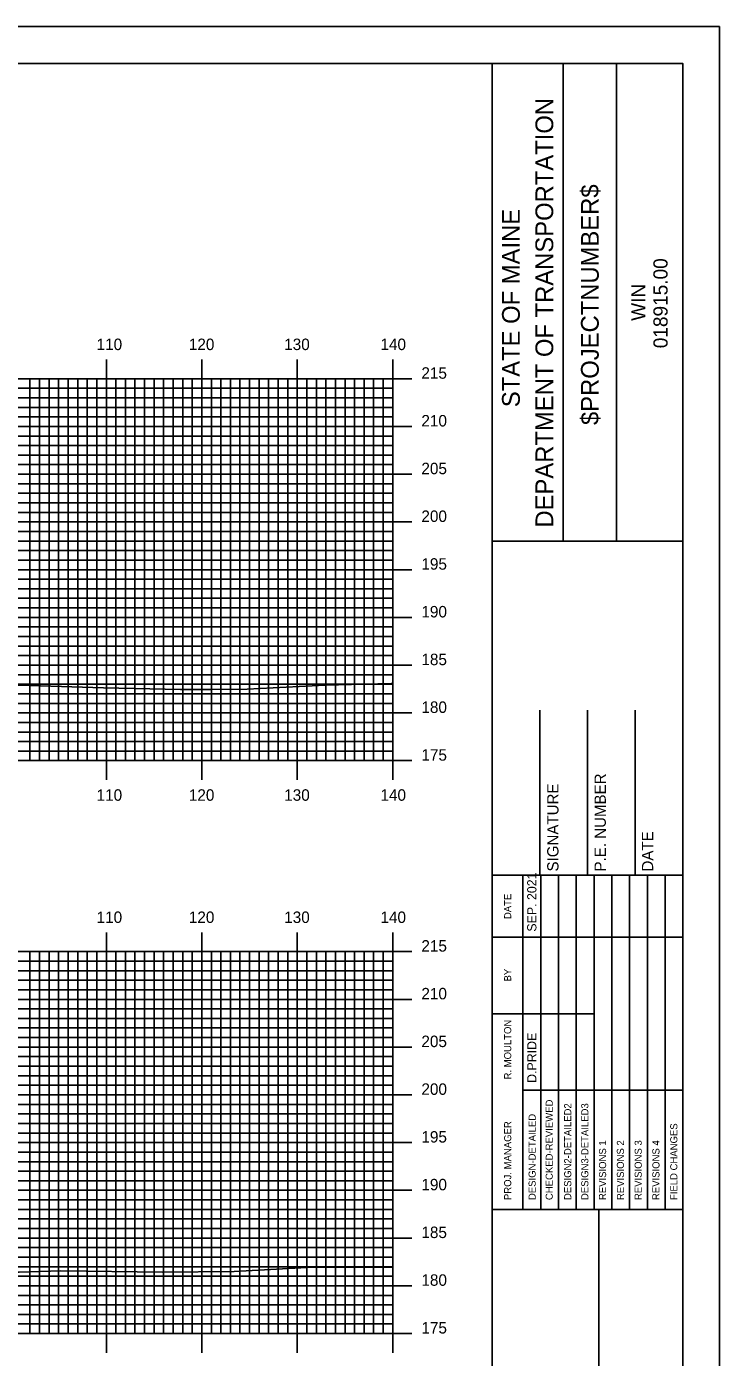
# Model space of a CAD drawing. Extents: x 1809800 to 1810143, y 442591 to 442811.
# Drawn here: x 1810067 to 1810139.6, y 442671.2 to 442810.5 of the extents above; entities that cross this region are included whole.
import ezdxf

# ---------------------------------------------------------------- set-up
doc = ezdxf.new("R2010")
doc.units = 0
for name, color, linetype in [('BORDER', 7, 'Continuous'), ('H_V ANNOTATION', 7, 'Continuous'), ('MAJOR', 7, 'Continuous'), ('MINOR', 7, 'Continuous'), ('PLOT BOUNDARY', 7, 'Continuous'), ('S_Roadway_Centerline', 7, 'Continuous')]:
    doc.layers.add(name, color=color, linetype=linetype)

msp = doc.modelspace()

# ---------------------------------------------------------------- linework, layer by layer
at = {"layer": 'BORDER'}
for p, q in [((1810115.75, 442596.67), (1810115.75, 442806.67)), ((1810123.21, 442756.66), (1810123.21, 442806.66)), ((1810128.8, 442756.66), (1810128.8, 442806.66)), ((1810115.75, 442756.65), (1810135.75, 442756.65)), ((1810120.75, 442721.67), (1810120.75, 442738.97)), ((1810125.75, 442721.67), (1810125.75, 442738.97)), ((1810130.75, 442721.67), (1810130.75, 442738.97)), ((1810115.75, 442721.67), (1810135.75, 442721.67)), ((1810115.75, 442686.67), (1810135.75, 442686.67)), ((1810126.93, 442616.67), (1810126.93, 442686.67))]:
    msp.add_line(p, q, dxfattribs=at)
msp.add_lwpolyline([(1809815.75, 442596.67), (1810135.75, 442596.67), (1810135.75, 442806.67), (1809815.75, 442806.67)], close=True, dxfattribs=at)
for points in [[(1810118.98, 442715.17), (1810118.98, 442721.67)], [(1810120.85, 442686.68), (1810120.85, 442721.67)], [(1810122.71, 442721.67), (1810122.71, 442686.68)], [(1810124.57, 442686.68), (1810124.57, 442721.67)], [(1810126.44, 442686.68), (1810126.44, 442721.67)], [(1810128.3, 442686.68), (1810128.3, 442721.67)], [(1810130.16, 442686.68), (1810130.16, 442721.67)], [(1810132.03, 442686.68), (1810132.03, 442721.67)], [(1810133.89, 442686.68), (1810133.89, 442721.67)], [(1810118.98, 442686.68), (1810118.98, 442720.26)], [(1810115.75, 442715.17), (1810135.75, 442715.17)], [(1810115.75, 442707.17), (1810118.98, 442707.17)], [(1810118.98, 442707.17), (1810126.43, 442707.17)], [(1810118.98, 442699.17), (1810135.75, 442699.17)]]:
    msp.add_lwpolyline(points, dxfattribs=at)
at = {"layer": 'MAJOR'}
for p, q in [((1810075.35, 442775.67), (1810075.35, 442773.67)), ((1810085.35, 442775.67), (1810085.35, 442773.67)), ((1810095.35, 442775.67), (1810095.35, 442773.67)), ((1810105.35, 442775.67), (1810105.35, 442773.67)), ((1809825.35, 442773.67), (1810105.35, 442773.67)), ((1809825.35, 442773.67), (1810105.35, 442773.67)), ((1810075.35, 442733.67), (1810075.35, 442773.67)), ((1810085.35, 442733.67), (1810085.35, 442773.67)), ((1810095.35, 442733.67), (1810095.35, 442773.67)), ((1810107.35, 442773.67), (1810103.35, 442773.67)), ((1810105.35, 442733.67), (1810105.35, 442773.67)), ((1810105.35, 442733.67), (1810105.35, 442773.67)), ((1809825.35, 442768.67), (1810105.35, 442768.67)), ((1810107.35, 442768.67), (1810103.35, 442768.67)), ((1809825.35, 442763.67), (1810105.35, 442763.67)), ((1810107.35, 442763.67), (1810103.35, 442763.67)), ((1809825.35, 442758.67), (1810105.35, 442758.67)), ((1810107.35, 442758.67), (1810103.35, 442758.67)), ((1809825.35, 442753.67), (1810105.35, 442753.67)), ((1810107.35, 442753.67), (1810103.35, 442753.67)), ((1809825.35, 442748.67), (1810105.35, 442748.67)), ((1810107.35, 442748.67), (1810103.35, 442748.67)), ((1809825.35, 442743.67), (1810105.35, 442743.67)), ((1810107.35, 442743.67), (1810103.35, 442743.67)), ((1809825.35, 442738.67), (1810105.35, 442738.67)), ((1810107.35, 442738.67), (1810103.35, 442738.67)), ((1809825.35, 442733.67), (1810105.35, 442733.67)), ((1809825.35, 442733.67), (1810105.35, 442733.67)), ((1810075.35, 442731.66), (1810075.35, 442733.67)), ((1810085.35, 442731.66), (1810085.35, 442733.67)), ((1810095.35, 442731.66), (1810095.35, 442733.67)), ((1810107.35, 442733.67), (1810103.35, 442733.67)), ((1810105.35, 442731.66), (1810105.35, 442733.67)), ((1810075.35, 442715.67), (1810075.35, 442713.67)), ((1810085.35, 442715.67), (1810085.35, 442713.67)), ((1810095.35, 442715.67), (1810095.35, 442713.67)), ((1810105.35, 442715.67), (1810105.35, 442713.67)), ((1809825.35, 442713.67), (1810105.35, 442713.67)), ((1809825.35, 442713.67), (1810105.35, 442713.67)), ((1810075.35, 442673.67), (1810075.35, 442713.67)), ((1810085.35, 442673.67), (1810085.35, 442713.67)), ((1810095.35, 442673.67), (1810095.35, 442713.67)), ((1810107.35, 442713.67), (1810103.35, 442713.67)), ((1810105.35, 442673.67), (1810105.35, 442713.67)), ((1810105.35, 442673.67), (1810105.35, 442713.67)), ((1809825.35, 442708.67), (1810105.35, 442708.67)), ((1810107.35, 442708.67), (1810103.35, 442708.67)), ((1809825.35, 442703.67), (1810105.35, 442703.67)), ((1810107.35, 442703.67), (1810103.35, 442703.67)), ((1809825.35, 442698.67), (1810105.35, 442698.67)), ((1810107.35, 442698.67), (1810103.35, 442698.67)), ((1809825.35, 442693.67), (1810105.35, 442693.67)), ((1810107.35, 442693.67), (1810103.35, 442693.67)), ((1809825.35, 442688.67), (1810105.35, 442688.67)), ((1810107.35, 442688.67), (1810103.35, 442688.67)), ((1809825.35, 442683.67), (1810105.35, 442683.67)), ((1810107.35, 442683.67), (1810103.35, 442683.67)), ((1809825.35, 442678.67), (1810105.35, 442678.67)), ((1810107.35, 442678.67), (1810103.35, 442678.67)), ((1809825.35, 442673.67), (1810105.35, 442673.67)), ((1809825.35, 442673.67), (1810105.35, 442673.67)), ((1810075.35, 442671.66), (1810075.35, 442673.67)), ((1810085.35, 442671.66), (1810085.35, 442673.67)), ((1810095.35, 442671.66), (1810095.35, 442673.67)), ((1810107.35, 442673.67), (1810103.35, 442673.67)), ((1810105.35, 442671.66), (1810105.35, 442673.67))]:
    msp.add_line(p, q, dxfattribs=at)
at = {"layer": 'MINOR'}
for p, q in [((1810067.35, 442733.67), (1810067.35, 442773.67)), ((1810068.35, 442733.67), (1810068.35, 442773.67)), ((1810069.35, 442733.67), (1810069.35, 442773.67)), ((1810070.35, 442733.67), (1810070.35, 442773.67)), ((1810071.35, 442733.67), (1810071.35, 442773.67)), ((1810072.35, 442733.67), (1810072.35, 442773.67)), ((1810073.35, 442733.67), (1810073.35, 442773.67)), ((1810074.35, 442733.67), (1810074.35, 442773.67)), ((1810076.35, 442733.67), (1810076.35, 442773.67)), ((1810077.35, 442733.67), (1810077.35, 442773.67)), ((1810078.35, 442733.67), (1810078.35, 442773.67)), ((1810079.35, 442733.67), (1810079.35, 442773.67)), ((1810080.35, 442733.67), (1810080.35, 442773.67)), ((1810081.35, 442733.67), (1810081.35, 442773.67)), ((1810082.35, 442733.67), (1810082.35, 442773.67)), ((1810083.35, 442733.67), (1810083.35, 442773.67)), ((1810084.35, 442733.67), (1810084.35, 442773.67)), ((1810086.35, 442733.67), (1810086.35, 442773.67)), ((1810087.35, 442733.67), (1810087.35, 442773.67)), ((1810088.35, 442733.67), (1810088.35, 442773.67)), ((1810089.35, 442733.67), (1810089.35, 442773.67)), ((1810090.35, 442733.67), (1810090.35, 442773.67)), ((1810091.35, 442733.67), (1810091.35, 442773.67)), ((1810092.35, 442733.67), (1810092.35, 442773.67)), ((1810093.35, 442733.67), (1810093.35, 442773.67)), ((1810094.35, 442733.67), (1810094.35, 442773.67)), ((1810096.35, 442733.67), (1810096.35, 442773.67)), ((1810097.35, 442733.67), (1810097.35, 442773.67)), ((1810098.35, 442733.67), (1810098.35, 442773.67)), ((1810099.35, 442733.67), (1810099.35, 442773.67)), ((1810100.35, 442733.67), (1810100.35, 442773.67)), ((1810101.35, 442733.67), (1810101.35, 442773.67)), ((1810102.35, 442733.67), (1810102.35, 442773.67)), ((1810103.35, 442733.67), (1810103.35, 442773.67)), ((1810104.35, 442733.67), (1810104.35, 442773.67)), ((1809825.35, 442772.67), (1810105.35, 442772.67)), ((1809825.35, 442771.67), (1810105.35, 442771.67)), ((1810105.35, 442772.67), (1810103.35, 442772.67)), ((1810105.35, 442771.67), (1810103.35, 442771.67)), ((1809825.35, 442770.67), (1810105.35, 442770.67)), ((1810105.35, 442770.67), (1810103.35, 442770.67)), ((1809825.35, 442769.67), (1810105.35, 442769.67)), ((1810105.35, 442769.67), (1810103.35, 442769.67)), ((1809825.35, 442767.67), (1810105.35, 442767.67)), ((1810105.35, 442767.67), (1810103.35, 442767.67)), ((1809825.35, 442766.67), (1810105.35, 442766.67)), ((1810105.35, 442766.67), (1810103.35, 442766.67)), ((1809825.35, 442765.67), (1810105.35, 442765.67)), ((1809825.35, 442764.67), (1810105.35, 442764.67)), ((1810105.35, 442765.67), (1810103.35, 442765.67)), ((1810105.35, 442764.67), (1810103.35, 442764.67)), ((1809825.35, 442762.67), (1810105.35, 442762.67)), ((1809825.35, 442761.67), (1810105.35, 442761.67)), ((1810105.35, 442762.67), (1810103.35, 442762.67)), ((1810105.35, 442761.67), (1810103.35, 442761.67)), ((1809825.35, 442760.67), (1810105.35, 442760.67)), ((1810105.35, 442760.67), (1810103.35, 442760.67)), ((1809825.35, 442759.67), (1810105.35, 442759.67)), ((1810105.35, 442759.67), (1810103.35, 442759.67)), ((1809825.35, 442757.67), (1810105.35, 442757.67)), ((1810105.35, 442757.67), (1810103.35, 442757.67)), ((1809825.35, 442756.67), (1810105.35, 442756.67)), ((1810105.35, 442756.67), (1810103.35, 442756.67)), ((1809825.35, 442755.67), (1810105.35, 442755.67)), ((1809825.35, 442754.67), (1810105.35, 442754.67)), ((1810105.35, 442755.67), (1810103.35, 442755.67)), ((1810105.35, 442754.67), (1810103.35, 442754.67)), ((1809825.35, 442752.67), (1810105.35, 442752.67)), ((1810105.35, 442752.67), (1810103.35, 442752.67)), ((1809825.35, 442751.67), (1810105.35, 442751.67)), ((1809825.35, 442750.67), (1810105.35, 442750.67)), ((1810105.35, 442751.67), (1810103.35, 442751.67)), ((1810105.35, 442750.67), (1810103.35, 442750.67)), ((1809825.35, 442749.67), (1810105.35, 442749.67)), ((1810105.35, 442749.67), (1810103.35, 442749.67)), ((1809825.35, 442747.67), (1810105.35, 442747.67)), ((1810105.35, 442747.67), (1810103.35, 442747.67)), ((1809825.35, 442746.67), (1810105.35, 442746.67)), ((1810105.35, 442746.67), (1810103.35, 442746.67)), ((1809825.35, 442745.67), (1810105.35, 442745.67)), ((1810105.35, 442745.67), (1810103.35, 442745.67)), ((1809825.35, 442744.67), (1810105.35, 442744.67)), ((1810105.35, 442744.67), (1810103.35, 442744.67)), ((1809825.35, 442742.67), (1810105.35, 442742.67)), ((1810105.35, 442742.67), (1810103.35, 442742.67)), ((1809825.35, 442741.67), (1810105.35, 442741.67)), ((1810105.35, 442741.67), (1810103.35, 442741.67)), ((1809825.35, 442740.67), (1810105.35, 442740.67)), ((1809825.35, 442739.67), (1810105.35, 442739.67)), ((1810105.35, 442740.67), (1810103.35, 442740.67)), ((1810105.35, 442739.67), (1810103.35, 442739.67)), ((1809825.35, 442737.67), (1810105.35, 442737.67)), ((1809825.35, 442736.67), (1810105.35, 442736.67)), ((1810105.35, 442737.67), (1810103.35, 442737.67)), ((1810105.35, 442736.67), (1810103.35, 442736.67)), ((1809825.35, 442735.67), (1810105.35, 442735.67)), ((1810105.35, 442735.67), (1810103.35, 442735.67)), ((1809825.35, 442734.67), (1810105.35, 442734.67)), ((1810105.35, 442734.67), (1810103.35, 442734.67)), ((1810067.35, 442673.67), (1810067.35, 442713.67)), ((1810068.35, 442673.67), (1810068.35, 442713.67)), ((1810069.35, 442673.67), (1810069.35, 442713.67)), ((1810070.35, 442673.67), (1810070.35, 442713.67)), ((1810071.35, 442673.67), (1810071.35, 442713.67)), ((1810072.35, 442673.67), (1810072.35, 442713.67)), ((1810073.35, 442673.67), (1810073.35, 442713.67)), ((1810074.35, 442673.67), (1810074.35, 442713.67)), ((1810076.35, 442673.67), (1810076.35, 442713.67)), ((1810077.35, 442673.67), (1810077.35, 442713.67)), ((1810078.35, 442673.67), (1810078.35, 442713.67)), ((1810079.35, 442673.67), (1810079.35, 442713.67)), ((1810080.35, 442673.67), (1810080.35, 442713.67)), ((1810081.35, 442673.67), (1810081.35, 442713.67)), ((1810082.35, 442673.67), (1810082.35, 442713.67)), ((1810083.35, 442673.67), (1810083.35, 442713.67)), ((1810084.35, 442673.67), (1810084.35, 442713.67)), ((1810086.35, 442673.67), (1810086.35, 442713.67)), ((1810087.35, 442673.67), (1810087.35, 442713.67)), ((1810088.35, 442673.67), (1810088.35, 442713.67)), ((1810089.35, 442673.67), (1810089.35, 442713.67)), ((1810090.35, 442673.67), (1810090.35, 442713.67)), ((1810091.35, 442673.67), (1810091.35, 442713.67)), ((1810092.35, 442673.67), (1810092.35, 442713.67)), ((1810093.35, 442673.67), (1810093.35, 442713.67)), ((1810094.35, 442673.67), (1810094.35, 442713.67)), ((1810096.35, 442673.67), (1810096.35, 442713.67)), ((1810097.35, 442673.67), (1810097.35, 442713.67)), ((1810098.35, 442673.67), (1810098.35, 442713.67)), ((1810099.35, 442673.67), (1810099.35, 442713.67)), ((1810100.35, 442673.67), (1810100.35, 442713.67)), ((1810101.35, 442673.67), (1810101.35, 442713.67)), ((1810102.35, 442673.67), (1810102.35, 442713.67)), ((1810103.35, 442673.67), (1810103.35, 442713.67)), ((1810104.35, 442673.67), (1810104.35, 442713.67)), ((1809825.35, 442712.67), (1810105.35, 442712.67)), ((1809825.35, 442711.67), (1810105.35, 442711.67)), ((1810105.35, 442712.67), (1810103.35, 442712.67)), ((1810105.35, 442711.67), (1810103.35, 442711.67)), ((1809825.35, 442710.67), (1810105.35, 442710.67)), ((1810105.35, 442710.67), (1810103.35, 442710.67)), ((1809825.35, 442709.67), (1810105.35, 442709.67)), ((1810105.35, 442709.67), (1810103.35, 442709.67)), ((1809825.35, 442707.67), (1810105.35, 442707.67)), ((1810105.35, 442707.67), (1810103.35, 442707.67)), ((1809825.35, 442706.67), (1810105.35, 442706.67)), ((1810105.35, 442706.67), (1810103.35, 442706.67)), ((1809825.35, 442705.67), (1810105.35, 442705.67)), ((1809825.35, 442704.67), (1810105.35, 442704.67)), ((1810105.35, 442705.67), (1810103.35, 442705.67)), ((1810105.35, 442704.67), (1810103.35, 442704.67)), ((1809825.35, 442702.67), (1810105.35, 442702.67)), ((1809825.35, 442701.67), (1810105.35, 442701.67)), ((1810105.35, 442702.67), (1810103.35, 442702.67)), ((1810105.35, 442701.67), (1810103.35, 442701.67)), ((1809825.35, 442700.67), (1810105.35, 442700.67)), ((1810105.35, 442700.67), (1810103.35, 442700.67)), ((1809825.35, 442699.67), (1810105.35, 442699.67)), ((1810105.35, 442699.67), (1810103.35, 442699.67)), ((1809825.35, 442697.67), (1810105.35, 442697.67)), ((1810105.35, 442697.67), (1810103.35, 442697.67)), ((1809825.35, 442696.67), (1810105.35, 442696.67)), ((1810105.35, 442696.67), (1810103.35, 442696.67)), ((1809825.35, 442695.67), (1810105.35, 442695.67)), ((1810105.35, 442695.67), (1810103.35, 442695.67)), ((1809825.35, 442694.67), (1810105.35, 442694.67)), ((1810105.35, 442694.67), (1810103.35, 442694.67)), ((1809825.35, 442692.67), (1810105.35, 442692.67)), ((1810105.35, 442692.67), (1810103.35, 442692.67)), ((1809825.35, 442691.67), (1810105.35, 442691.67)), ((1809825.35, 442690.67), (1810105.35, 442690.67)), ((1810105.35, 442691.67), (1810103.35, 442691.67)), ((1810105.35, 442690.67), (1810103.35, 442690.67)), ((1809825.35, 442689.67), (1810105.35, 442689.67)), ((1810105.35, 442689.67), (1810103.35, 442689.67)), ((1809825.35, 442687.67), (1810105.35, 442687.67)), ((1809825.35, 442686.67), (1810105.35, 442686.67)), ((1810105.35, 442687.67), (1810103.35, 442687.67)), ((1810105.35, 442686.67), (1810103.35, 442686.67)), ((1809825.35, 442685.67), (1810105.35, 442685.67)), ((1810105.35, 442685.67), (1810103.35, 442685.67)), ((1809825.35, 442684.67), (1810105.35, 442684.67)), ((1810105.35, 442684.67), (1810103.35, 442684.67)), ((1809825.35, 442682.67), (1810105.35, 442682.67)), ((1810105.35, 442682.67), (1810103.35, 442682.67)), ((1809825.35, 442681.67), (1810105.35, 442681.67)), ((1810105.35, 442681.67), (1810103.35, 442681.67)), ((1809825.35, 442680.67), (1810105.35, 442680.67)), ((1809825.35, 442679.67), (1810105.35, 442679.67)), ((1810105.35, 442680.67), (1810103.35, 442680.67)), ((1810105.35, 442679.67), (1810103.35, 442679.67)), ((1809825.35, 442677.67), (1810105.35, 442677.67)), ((1809825.35, 442676.67), (1810105.35, 442676.67)), ((1810105.35, 442677.67), (1810103.35, 442677.67)), ((1810105.35, 442676.67), (1810103.35, 442676.67)), ((1809825.35, 442675.67), (1810105.35, 442675.67)), ((1810105.35, 442675.67), (1810103.35, 442675.67)), ((1809825.35, 442674.67), (1810105.35, 442674.67)), ((1810105.35, 442674.67), (1810103.35, 442674.67))]:
    msp.add_line(p, q, dxfattribs=at)
at = {"layer": 'PLOT BOUNDARY'}
msp.add_lwpolyline([(1809799.56, 442590.55), (1810139.56, 442590.55), (1810139.56, 442810.55), (1809799.56, 442810.55)], close=True, dxfattribs=at)
at = {"layer": 'S_Roadway_Centerline'}
for points in [[(1809993.6, 442742), (1809995.7, 442742.05), (1810005.16, 442742.06), (1810013.66, 442741.94), (1810018.07, 442741.86), (1810021.46, 442741.74), (1810035.66, 442741.82), (1810043.28, 442741.89), (1810051.49, 442741.71), (1810059.59, 442741.63), (1810063.53, 442741.62), (1810067.32, 442741.54), (1810075.07, 442741.3), (1810083.13, 442741.11), (1810086.44, 442741.11), (1810090.1, 442741.14), (1810098.28, 442741.56), (1810105.2, 442741.75), (1810105.35, 442741.76)], [(1809993.93, 442680.26), (1810003.99, 442680.43), (1810014.37, 442680.43), (1810017.95, 442680.39), (1810036.88, 442680.32), (1810039.01, 442680.3), (1810040.95, 442680.35), (1810058.44, 442680.09), (1810066.22, 442680.11), (1810070.57, 442680.24), (1810081.23, 442680.08), (1810088.74, 442680.15), (1810096.97, 442680.62), (1810103.86, 442680.61), (1810105.35, 442680.63)]]:
    msp.add_lwpolyline(points, dxfattribs=at)

# ---------------------------------------------------------------- texts
at = {"layer": 'BORDER'}
for s, height, p in [('DEPARTMENT OF TRANSPORTATION', 1.8635, (1810122.16, 442758.08)), ('$PROJECTNUMBER$', 1.8635, (1810126.93, 442768.82)), ('STATE OF MAINE', 1.8635, (1810118.66, 442770.69)), ('018915.00', 1.491, (1810134.14, 442776.86)), ('WIN', 1.491, (1810131.82, 442779.73)), ('SIGNATURE', 1.181, (1810122.71, 442722.06)), ('P.E. NUMBER', 1.1811, (1810127.67, 442722.06)), ('DATE', 1.181, (1810132.63, 442722.06)), ('SEP. 2021', 0.969, (1810120.4, 442715.76)), ('DATE', 0.743, (1810117.76, 442717.08)), ('BY', 0.743, (1810117.76, 442710.54)), ('R. MOULTON', 0.745, (1810117.76, 442700.28)), ('D.PRIDE', 0.969, (1810120.4, 442699.92)), ('CHECKED-REVIEWED', 0.7455, (1810122.11, 442687.65)), ('DESIGN2-DETAILED2', 0.7455, (1810124.05, 442687.65)), ('DESIGN3-DETAILED3', 0.7455, (1810125.84, 442687.65)), ('DESIGN-DETAILED', 0.7455, (1810120.32, 442687.65)), ('PROJ. MANAGER', 0.7455, (1810117.76, 442687.65)), ('FIELD CHANGES', 0.7455, (1810135.16, 442687.65)), ('REVISIONS 1', 0.7455, (1810127.7, 442687.65)), ('REVISIONS 2', 0.7455, (1810129.57, 442687.65)), ('REVISIONS 3', 0.7455, (1810131.43, 442687.65)), ('REVISIONS 4', 0.7455, (1810133.29, 442687.65))]:
    msp.add_text(s, height=height, rotation=90, dxfattribs=at).set_placement(p)
at = {"layer": 'H_V ANNOTATION'}
for s, p in [('110', (1810074.33, 442776.67)), ('120', (1810083.99, 442776.67)), ('130', (1810093.98, 442776.67)), ('140', (1810104.06, 442776.67)), ('215', (1810108.35, 442773.67)), ('210', (1810108.35, 442768.67)), ('205', (1810108.35, 442763.67)), ('200', (1810108.35, 442758.67)), ('195', (1810108.35, 442753.67)), ('190', (1810108.35, 442748.67)), ('185', (1810108.35, 442743.67)), ('180', (1810108.35, 442738.67)), ('175', (1810108.35, 442733.67)), ('110', (1810074.33, 442729.47)), ('120', (1810083.99, 442729.47)), ('130', (1810093.98, 442729.47)), ('140', (1810104.06, 442729.47)), ('110', (1810074.33, 442716.67)), ('120', (1810083.99, 442716.67)), ('130', (1810093.98, 442716.67)), ('140', (1810104.06, 442716.67)), ('215', (1810108.35, 442713.67)), ('210', (1810108.35, 442708.67)), ('205', (1810108.35, 442703.67)), ('200', (1810108.35, 442698.67)), ('195', (1810108.35, 442693.67)), ('190', (1810108.35, 442688.67)), ('185', (1810108.35, 442683.67)), ('180', (1810108.35, 442678.67)), ('175', (1810108.35, 442673.67))]:
    msp.add_text(s, height=1.2, dxfattribs=at).set_placement(p)

doc.saveas('drawing.dxf')
